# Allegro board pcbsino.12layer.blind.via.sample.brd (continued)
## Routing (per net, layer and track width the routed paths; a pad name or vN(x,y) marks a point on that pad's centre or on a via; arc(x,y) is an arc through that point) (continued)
SODIMM_VIN4A_D7: length 35.7
  TOP w0.114: U6.A10 v2(33.65,17.51)
  INT_L3 w0.091: v3(33.74,16.99) 33.65,17.08 v2(33.65,17.51)
  SIG_L5 w0.091: v3(33.74,16.99) 33.42,16.67 33.42,15.71 34.51,14.62 42.62,14.62 46.47,18.46 46.47,20.13 46.83,20.49 v3(46.83,22.52)
  SIG_L10 w0.091: v5(46.74,22.92) 46.74,22.6 v3(46.83,22.52)
  BOTTOM w0.114: v5(46.74,22.92) 46.77,22.95 48.05,22.95 48.89,23.79 51.48,23.79 52.77,25.08 54.32,25.08 56.02,26.78 XP1.76
SODIMM_VIN4A_D8: length 55.2
  TOP w0.12: v8(35.87,20.77) U6.E8
  SIG_L5 w0.091: v3(46.9,45.5) 46.35,44.95 46.35,42.34
  SIG_L5 w0.094: v8(35.87,20.77) 36.29,20.35 36.29,17.31 37.31,16.29 42.12,16.29 44.32,18.48 44.32,21.75 44.72,22.15 44.72,24.73 45.61,25.62 45.61,25.8 46.35,26.54 46.35,42.34
  SIG_L10 w0.091: v3(46.9,45.5) v5(47.39,45.5)
  BOTTOM w0.114: XP1.124 54.58,41.18 51.2,44.56 50.28,44.56 49.32,45.53 47.42,45.53 v5(47.39,45.5)
SODIMM_VIN4A_D9: length 46
  TOP w0.12: v8(35.07,19.97) U6.D9
  SIG_L10 w0.091: v5(50.59,45.15) 49.63,45.15 44.66,40.17 44.66,39.99 44.66,35.2 44.9,34.95 44.9,34.77 44.9,24.38 44.79,24.27 43.39,22.86 43.02,22.86 42.09,22.86 41.94,22.86 41.26,22.18 41.26,22.13 40.3,21.17 35.61,21.17 35.48,21.04 35.48,20.38 v8(35.07,19.97)
  BOTTOM w0.114: v5(50.59,45.15) 51.02,45.15 54.39,41.78 XP1.126
SODIMM_VIN4A_D10: length 47.4
  TOP w0.12: v8(36.67,19.97) U6.D7
  SIG_L10 w0.091: v5(52.34,44.46) 49.56,44.46 45.43,40.33 45.43,37.1 46.06,36.47 46.06,34.28 45.36,33.58 45.36,23.93 46.09,23.21 46.09,22.17 46.08,22.17 46.08,20.63 45.23,19.77 40.45,19.77 39.92,20.31 39.23,20.31 38.5,19.57 37.07,19.57 v8(36.67,19.97)
  BOTTOM w0.114: v5(52.34,44.46) 52.9,44.46 54.93,42.43 58.58,42.43 XP1.128
SODIMM_VIN4A_D11: length 44.2
  TOP w0.12: v8(35.87,19.97) U6.D8
  SIG_L10 w0.091: v8(35.87,19.97) 36.24,20.35 36.82,20.35 37.19,20.71 40.16,20.71 41.48,22.04 41.48,22.09 42.03,22.64 43.11,22.64 43.48,22.64 44.34,23.5 45.14,24.31 45.14,35.02 44.87,35.29 44.87,40.08 49.59,44.79 v5(52.6,44.79)
  BOTTOM w0.114: v5(52.6,44.79) 53.05,44.79 55.06,42.79 57.04,42.79 57.23,42.98 XP1.130
SODIMM_VIN4A_D12: length 46.6
  TOP w0.12: U6.A5 37.87,17.62 v2(37.79,17.54) 37.79,17.53 37.78,17.53
  INT_L3 w0.091: v2(37.79,17.54) 38.22,17.54 v3(38.27,17.49)
  SIG_L10 w0.091: v3(38.27,17.49) 39.36,16.4 43.35,16.4 47.97,21.02 47.97,26.02 47.28,26.72 46.3,27.7 46.3,29.48 46.03,29.75 46.03,33.32 46.46,33.76 46.72,34.01 46.72,36.2 46.72,36.74 46.09,37.37 46.09,40.06 49.7,43.68 55.72,43.68 56.25,44.21 v5(57.55,44.21)
SODIMM_VIN4A_D13: length 47.4
  TOP w0.12: U6.C6 37.07,19.45 37.35,19.17 v8(37.47,19.17)
  SIG_L10 w0.091: v8(37.47,19.17) 38.29,19.17 39.22,18.24 44.35,18.24 47.44,21.33 47.44,25.8 45.99,27.25 45.59,27.65 45.59,33.5 46.28,34.19 46.28,36.56 45.65,37.19 45.65,40.24 49.54,44.13 55.41,44.13 56.1,44.82 v5(56.94,44.82)
  BOTTOM w0.114: XP1.136 57.03,44.78 56.99,44.82 v5(56.94,44.82)
SODIMM_VIN4A_D14: length 52
  TOP w0.12: v8(35.87,19.17) U6.C8
  SIG_L10 w0.091: v5(58.13,45.38) 58.12,45.36 58.12,44.35 57.47,43.7 56.15,43.7 55.91,43.46 49.79,43.46 46.31,39.97 46.31,37.46 46.94,36.83 46.94,36.11 46.94,33.92 46.42,33.41 46.25,33.23 46.25,29.84 46.51,29.57 46.51,27.79 47.37,26.94 48.19,26.11 48.19,20.91 43.47,16.18 37.5,16.18 36.27,17.41 36.27,18.34 35.87,18.75 v8(35.87,19.17)
SODIMM_VIN4A_D15: length 48.6
  TOP w0.12: v8(36.67,19.17) U6.C7
  SIG_L10 w0.091: v8(36.67,19.17) 36.81,19.17 37.24,18.75 38,18.75 38.73,18.02 44.59,18.02 47.74,21.17 47.74,25.81 46.08,27.47 46.08,29.39 45.81,29.66 45.81,33.41 46.37,33.98 46.5,34.1 46.5,36.29 46.5,36.65 45.87,37.28 45.87,40.15 49.63,43.91 55.55,43.91 56.13,44.49 57.19,44.49 57.65,44.95 57.65,45.97 v5(57.68,45.99)
SODIMM_VIN4A_D16: length 48.3
  TOP w0.114: U6.F11 v8(33.47,21.57)
  SIG_L10 w0.091: v4(41.58,40.63) 41.93,40.28 41.93,33.9 42.1,33.73 42.1,29.68 40.81,28.38 37.79,28.38 35.48,26.07 34.13,26.07 33.85,25.79 33.85,24.53 32.88,23.56 32.25,23.56 31.46,22.77 31.46,22.1 31.62,21.94 32.93,21.94 33.3,21.57 v8(33.47,21.57)
  GND_L11 w0.091: v5(41.72,40.98) v4(41.58,40.63)
  BOTTOM w0.114: v5(41.72,40.98) 50.23,40.98 53.33,37.88 54.8,37.88 56.91,35.78 XP1.106
SODIMM_VIN4A_D17: length 42.7
  TOP w0.12: U6.G10 v8(34.27,22.37)
  SIG_L10 w0.091: v5(44.52,42.2) 43.44,41.12 43.44,39.11 42.59,38.27 42.59,34.17 42.84,33.92 42.84,29.25 39.79,26.2 38.24,26.2 37.92,25.87 37.92,25.24 37.61,24.93 37.36,24.93 35.22,22.8 34.69,22.8 v8(34.27,22.37)
  BOTTOM w0.114: XP1.108 56.77,36.38 55.02,38.13 53.65,38.13 50.18,41.59 45.13,41.59 v5(44.52,42.2)
SODIMM_VIN4A_D18: length 46.5
  TOP w0.114: U6.F10 v8(34.27,21.57)
  SIG_L10 w0.091: v8(34.27,21.57) 34.31,21.57 34.73,22 35.22,22 35.44,22.22 35.44,22.54 36.49,23.58 40.25,23.58 40.47,23.8 43.09,23.8 43.88,24.6 43.88,34.74 43.78,34.84 43.78,39.63 43.78,40.91 44.95,42.08 v5(44.95,42.81)
  BOTTOM w0.114: XP1.110 56.6,36.98 55.21,38.37 53.96,38.37 50.27,42.05 45.71,42.05 v5(44.95,42.81)
SODIMM_VIN4A_D19: length 45.7
  TOP w0.114: U6.G11 v8(33.47,22.37)
  SIG_L10 w0.091: v8(33.47,22.37) 33.88,22.78 33.88,23.39 34.08,23.59 34.92,23.59 35.09,23.76 35.09,24.04 34.92,24.22 34.92,24.79 35.29,25.16 36.8,25.16 37.08,25.44 37.08,25.74 37.86,26.53 39.81,26.53 42.56,29.28 42.56,33.89 42.37,34.08 42.37,41.22 44.82,43.68 v5(45.41,43.68)
  BOTTOM w0.114: v5(45.41,43.68) 46.55,42.53 50.15,42.53 54.07,38.61 55.39,38.61 56.42,37.58 XP1.112
SODIMM_VIN4A_D20: length 58.1
  TOP w0.12: v8(35.07,20.77) U6.E9
  SIG_L5 w0.094: v3(48,45) 46.79,43.79 46.79,34.34 46.79,33.8 46.79,32.22 46.79,27.81 46.81,27.79 46.81,25.2 45.53,23.92 45.53,22.03 44.98,21.48 44.98,18.21 42.26,15.49 36.6,15.49 35.84,16.25 35.84,16.85 35.33,17.36 35.33,18.04 35.47,18.19 35.47,20.37 v8(35.07,20.77)
  SIG_L10 w0.091: v5(47.77,44.21) 48,44.44 v3(48,45)
  BOTTOM w0.114: XP1.116 55.89,38.78 55.64,39.03 53.99,39.03 48.81,44.21 v5(47.77,44.21)
SODIMM_VIN4A_D21: length 45.9
  TOP w0.12: v8(35.07,21.57) U6.F9
  SIG_L10 w0.091: v5(47.06,44.23) 47.06,43.78 44,40.72 44,40.44 44,34.93 44.14,34.79 44.14,24.54 43.18,23.58 43,23.58 40.56,23.58 40.25,23.28 39.71,23.28 39.22,22.8 37.31,22.8 37.3,22.81 36.53,22.81 36.24,22.53 36.24,22.22 36.02,22 35.53,22 35.11,21.57 v8(35.07,21.57)
  BOTTOM w0.114: v5(47.06,44.23) 47.34,44.51 48.85,44.51 53.98,39.38 XP1.118
SODIMM_VIN4A_D22: length 44.8
  TOP w0.12: U6.F8 35.83,21.61 35.83,21.57 v8(35.84,21.56)
  SIG_L10 w0.091: v5(48.79,44.84) 48.79,44.64 44.44,40.29 44.44,40.26 44.44,35.11 44.69,34.86 44.69,24.47 44.57,24.36 43.3,23.08 43.11,23.08 42.18,23.08 41.81,23.08 41.04,22.32 41.04,22.22 40.78,21.96 36.47,21.96 36.08,21.57 35.85,21.57 v8(35.84,21.56)
  BOTTOM w0.114: v5(48.79,44.84) 48.94,44.84 53.8,39.98 XP1.120
SODIMM_VIN4A_D23: length 45.9
  TOP w0.12: v8(36.67,20.77) U6.E7
  SIG_L5 w0.091: v8(36.67,20.77) 37.04,21.15 37.04,22.53 37.02,22.55 37.02,25.17 37.1,25.25 37.1,25.85 37.01,25.94 37.01,27.93 36.8,28.15 36.65,28.15 35.48,29.32 35.48,32.91 35.49,32.92 35.49,32.93 35.71,33.15 35.72,33.15 36.01,33.44 36.01,33.92 37.09,35 37.09,35.33 37.31,35.55 38.5,35.55 38.69,35.74 38.69,36.13 38.91,36.35 39.3,36.35 39.52,36.57 39.52,37.06 40.53,38.06 41.55,38.06 v3(42.79,39.31)
  SIG_L10 w0.091: v3(42.79,39.31) 42.79,41.21 44.82,43.24 45.53,43.24 47.11,44.82 v5(47.11,44.92)
  BOTTOM w0.114: XP1.122 53.66,40.58 49.09,45.15 47.39,45.15 47.16,44.92 v5(47.11,44.92)
SODIMM_VIN4A_DE0: length 50.5
  TOP w0.114: v2(34.15,18.48) 33.87,18.77 U6.B10
  INT_L3 w0.091: v3(34.24,17.92) 34.15,18 v2(34.15,18.48)
  SIG_L5 w0.091: v3(47.87,37.76) 47.25,37.14 47.25,24.49 46.43,23.67 46.43,20.4 46.25,20.22 46.25,18.55 42.53,14.84 34.6,14.84 34.23,15.21 34.23,15.54 34.24,15.54 v3(34.24,17.92)
  SIG_L10 w0.091: v3(47.87,37.76) 47.87,38.44 v5(48,38.57)
  BOTTOM w0.114: v5(48,38.57) 48.3,38.88 50.87,38.88 52.1,37.64 54.64,37.64 57.1,35.18 XP1.104
SODIMM_VIN4A_FLD0: length 54.3
  TOP w0.12: v8(33.5,19.88) 33.49,19.88 33.49,19.95 U6.D11
  SIG_L10 w0.091: v5(48.33,37.07) 48.05,36.8 48.05,34.04 48.05,33.5 47.84,33.28 47.34,32.78 47.34,30.29 48.02,29.6 48.02,28.05 49.53,26.55 49.53,20.57 43.68,14.72 34.23,14.72 33.32,15.63 33.32,17.81 34,18.5 34,19.37 v8(33.5,19.88)
  BOTTOM w0.114: v5(48.33,37.07) 48.33,37.03 48.59,36.77 54.12,36.77 56.61,34.28 56.61,33.9 57.13,33.38 XP1.98
SODIMM_VIN4A_HSYNC0: length 52
  TOP w0.12: v8(33.51,19.23) 33.49,19.24 33.4,19.24 U6.C11
  SIG_L5 w0.091: v8(33.51,19.23) 33.62,19.12 33.62,17.48 33,16.86 33,15.47 34.06,14.4 42.9,14.4 46.69,18.19 46.69,20.04 47.47,20.82 47.47,34.02 48.59,35.14 49.48,35.14 50.46,36.12 50.46,37.62 v3(50.29,37.79)
  SIG_L10 w0.091: v3(50.29,37.79) 50.77,37.79 v5(50.77,37.78)
  BOTTOM w0.114: v5(50.77,37.78) 50.85,37.71 50.87,37.71 51.48,37.1 54.17,37.1 57.29,33.98 XP1.100
SODIMM_VIN4A_VSYNC0: length 55.5
  TOP w0.12: v8(33.47,20.77) U6.E11
  SIG_L10 w0.091: v8(33.47,20.77) 33.47,20.51 34.41,19.57 34.41,18.43 34.66,18.17 34.66,17.16 34.23,16.73 34.23,15.15 34.44,14.94 43.59,14.94 49.31,20.66 49.31,26.21 49.28,26.24 49.28,26.26 47.73,27.81 47.73,29.59 47.12,30.2 47.12,32.87 47.84,33.59 47.84,33.95 47.84,37.06 48.27,37.5 48.27,38.29 v5(48.48,38.49)
  BOTTOM w0.114: XP1.102 57.17,34.58 54.4,37.35 51.91,37.35 50.69,38.57 48.56,38.57 v5(48.48,38.49)
SODIMM_VIN5A_D8: length 55.4
  TOP w0.12: v8(39.07,34.37) U6.AA4
  INT_L3 w0.091: v2(57.7,4.59) 58.11,4.59 58.64,4.05 58.64,2.22 57.85,1.44 v3(56.53,1.44)
  SIG_L8 w0.091: v8(39.07,34.37) 39.49,33.95 40.27,33.95 40.48,33.74 45.01,33.74 46.85,35.59 49.33,35.59 49.6,35.85 v3(49.6,35.9)
  SIG_L10 w0.091: v3(49.6,35.9) 51.65,33.85 51.65,22.3 51.9,22.05 52.03,21.92 52.03,21.27 52.03,21.26 52.03,20.83 52.03,20.83 52.03,18.34 51.76,18.07 51.63,17.94 51.63,11.41 54.04,9 54.04,4.86 56.38,2.53 56.38,1.59 v3(56.53,1.44)
SODIMM_VIN5A_D9: length 53
  TOP w0.12: v8(39.87,35.17) U6.AB3
  INT_L3 w0.091: v2(57.95,3.98) 58.18,3.98 58.41,3.75 58.41,2.43 57.73,1.74 56.79,1.74 56.7,1.84 56.69,1.84 56.3,2.22 v3(55.95,2.22)
  SIG_L8 w0.091: v8(39.87,35.17) 40.82,34.22 44.86,34.22 46.81,36.16 48.31,36.16 48.35,36.21 v3(48.45,36.21)
  SIG_L10 w0.091: v3(55.95,2.22) 55.87,2.3 55.87,2.53 53.82,4.57 53.82,8.77 51.27,11.32 51.27,17.89 51.41,18.03 51.81,18.43 51.81,20.92 51.81,20.92 51.81,21.17 51.81,21.18 51.81,21.83 51.67,21.97 51.05,22.59 51.05,30.47 50.59,30.92 50.59,34.25 49.14,35.7 49.14,35.93 48.86,36.21 v3(48.45,36.21)
SODIMM_VIN5A_D10: length 52
  TOP w0.114: XP1.3 56.51,2.78 v2(56.48,2.81) ; U6.AB9 v2(35.07,35.14)
  INT_L3 w0.091: v2(35.07,35.14) 35.04,35.14 34.89,35 34.89,34.56 v3(34.88,34.55) ; v3(41.77,11.09) 41.72,11.04 41.72,9.92 43.45,8.19 46.63,8.19 46.85,7.97 46.85,6.65 47.79,5.71 50.43,5.71 52.12,4.02 52.13,4.02 52.36,3.79 52.36,3.78 52.54,3.59 54.5,3.59 54.71,3.39 54.73,3.38 54.99,3.21 55.2,2.99 55.32,2.81 v2(56.48,2.81)
  SIG_L8 w0.091: v3(41.77,11.09) 42.66,11.98 42.66,15.61 41.09,17.18 41.09,17.81 38.79,20.11 38.79,20.91 37.74,21.96 37.18,21.96 37.08,22.06 37.08,28.69 36.34,29.43 36.34,29.75 35.4,30.7 34.89,30.7 34.64,30.94 34.64,31.33 34.42,31.55 34.04,31.55 33.85,31.73 33.85,33.72 34.13,34 34.43,34 34.88,34.44 v3(34.88,34.55)
SODIMM_VIN5A_D11: length 50.4
  TOP w0.12: v8(39.83,34.34) U6.AA3
  INT_L3 w0.091: v2(58.01,3.39) 58.01,2.91 v3(57.83,2.73)
  SIG_L8 w0.091: v8(39.83,34.34) 40.27,34.34 40.61,34 44.95,34 46.76,35.81 48.87,35.81 49.39,36.34 50,36.34 v3(50.06,36.28)
  SIG_L10 w0.091: v3(50.06,36.28) 51.87,34.47 51.87,22.39 51.99,22.27 52.24,22.01 52.24,21.36 52.25,21.35 52.25,20.74 52.24,20.74 52.24,18.25 51.99,17.99 51.85,17.85 51.85,11.5 54.35,9 54.35,5.02 56.63,2.73 v3(57.83,2.73)
SODIMM_VIN5A_D12: length 51.9
  TOP w0.12: v8(27.87,19.97) U6.D17
  INT_L3 w0.091: v3(44.04,6.97) 44.34,6.97 44.85,6.46 44.85,3.24 47.66,0.43 58.04,0.43 59.3,1.68 59.3,2.01 59.3,5.56 58.82,6.03 v2(58.82,7)
  SIG_L10 w0.091: v8(27.87,19.97) 27.99,19.97 28.6,19.36 28.6,12.65 29.48,11.78 30.27,11.78 34.86,7.19 43.82,7.19 v3(44.04,6.97)
SODIMM_VIN5A_D13: length 45.2
  TOP w0.114: XP1.15 v2(57.53,6.38)
  TOP w0.12: v8(28.67,22.37) U6.G16
  INT_L3 w0.091: v2(57.53,6.38) 56.74,6.38 56.42,6.06 53.54,6.06 v3(53.34,5.87)
  SIG_L10 w0.091: v3(53.34,5.87) 51.79,5.87 51.52,6.14 47.17,6.14 46.73,5.71 44.91,5.71 44.11,6.52 43.53,6.52 43.44,6.61 36.63,6.61 36.3,6.95 36.12,6.95 34.79,6.95 30.18,11.56 29.39,11.56 28.38,12.56 28.38,19.19 28.02,19.55 27.71,19.55 27.47,19.79 27.47,20.94 27.73,21.2 28.09,21.2 28.29,21.41 28.29,21.96 28.67,22.34 v8(28.67,22.37)
SODIMM_VIN5A_D14: length 50.8
  TOP w0.114: U6.A21 25.87,17.17 25.87,14.06 v2(25.32,13.5)
  INT_L3 w0.091: v3(24.78,13.42) 24.86,13.5 v2(25.32,13.5) ; v3(45.76,4.33) 45.82,4.33 46.6,5.11 50.14,5.11 51.56,3.69 51.56,3.13 51.71,2.98 53.11,2.98 53.16,3.04 53.38,3.18 53.62,3.28 53.87,3.33 54.13,3.33 54.39,3.28 54.63,3.18 54.85,3.04 55.03,2.85 55.18,2.64 55.28,2.4 55.33,2.14 55.33,1.56 56,0.89 57.72,0.89 58.86,2.03 58.86,4.37 v2(58.06,5.17)
  SIG_L10 w0.091: v3(45.76,4.33) 43.76,4.33 43.1,4.99 34.04,4.99 33.88,4.83 33.15,4.83 32.18,5.81 32.08,5.81 24.78,13.11 v3(24.78,13.42)
SODIMM_VIN5A_D15: length 50
  TOP w0.12: v8(27.04,19.22) 27.05,19.22 27.07,19.24 27.13,19.24 U6.C18
  INT_L3 w0.091: v2(58.06,5.8) 59.08,4.78 59.08,1.87 57.88,0.67 47.87,0.67 45.33,3.22 45.33,5.19 v3(45.41,5.27)
  SIG_L10 w0.091: v8(27.04,19.22) 27.37,18.89 27.37,14.96 27.27,14.85 27.27,13.04 33.57,6.74 34.68,6.74 34.7,6.73 36.21,6.73 36.54,6.39 43.35,6.39 43.44,6.3 43.92,6.3 44.98,5.25 45.38,5.25 v3(45.41,5.27)
SODIMM_WAKEUP1/GPIO1_1: length 53.4
  TOP w0.12: v8(27.87,35.97) U6.AC17
  SIG_L5 w0.091: v7(53.18,63.46) 52.62,63.46 51.53,62.37 51.53,54.98 49.57,53.02 45.38,53.02 42.24,49.88 42.24,49.2 41.22,48.17 41.22,44.82 40.83,44.44 31.77,44.44 29.07,41.75 29.07,36.36 28.69,35.97 v8(27.87,35.97)
  BOTTOM w0.114: XP1.192 55.52,61.58 R59.1 55.26,61.99 53.79,63.46 v7(53.18,63.46)
SODIMM_WARM_RESETN: length 90.3
  TOP w0.114: R54.2 20.02,3.68 C55.1 ; C55.1 21.23,3.68 21.52,3.96 v2(21.57,3.96) ; C55.1 20.62,3.94 U5.1 ; XP1.187 v2(57.95,60.38)
  INT_L3 w0.091: v3(21.81,4.38) 21.83,4.36 21.83,4.23 v2(21.57,3.96) ; v2(57.95,60.38) 57.95,60.37 57.95,60.09 v3(58.06,59.98)
  SIG_L5 w0.091: v3(58.06,59.98) 58.73,59.31 58.73,30.8 54.91,26.99 54.91,22.17 55.52,21.57 55.52,15.09 48.12,7.69 45.99,7.69 44.91,6.61 44.91,6.11 43.59,4.79 38.18,4.79 37.96,4.56 36.84,4.56 36.71,4.69 22.12,4.69 v3(21.81,4.38)
SYS_WARMRESETN: length 17.4
  TOP w0.114: v2(19.38,8.1) C59.1 18.22,7.83 U5.4
  TOP w0.12: v8(23.07,20.77) U6.E23
  INT_L3 w0.091: v8(23.07,20.77) 22.76,20.46 22.76,19.96 22.35,19.55 22.11,19.55 21.89,19.33 21.89,16.03 20.06,14.2 20.06,14.02 20.06,12.21 20.46,11.8 20.46,10.07 19.85,9.46 19.85,8.58 v2(19.38,8.1)
SYSBOOT0: length 2.3
  TOP w0.12: v8(37.46,27.19) 37.46,27.16 U6.M6
  BOTTOM w0.114: R224.2 R225.1 37.15,27.5 v8(37.46,27.19)
SYSBOOT1: length 6.3
  TOP w0.114: R222.2 R223.1 44.82,26.48 43.1,26.48 42.49,27.09 41.84,27.09 41.76,27.17 40.66,27.17 40.27,26.78 U6.M2
SYSBOOT2: length 3.4
  TOP w0.12: v8(38.3,25.56) 38.24,25.62 38.23,25.62 U6.L5
  BOTTOM w0.114: R220.2 R221.1 39.8,26.69 39.54,26.43 39.16,26.43 v8(38.3,25.56)
SYSBOOT3: length 7.4
  TOP w0.114: R218.2 47.48,25.36 R219.1
  TOP w0.12: R219.1 46.64,26.2 42.99,26.2 42.42,26.77 U6.M1
SYSBOOT4: length 39.7
  TOP w0.12: v8(37.48,25.56) U6.L6
  SIG_L5 w0.091: v3(52.09,50.75) 52.05,50.75 51.82,50.51 49.9,50.51 48.51,49.11 46.73,49.11 46.25,48.63 46.25,46.55 44.82,45.12 44.82,40.38 41.95,37.5 40.87,37.5 40.29,36.93 40.29,35.06 40.03,34.8 37.29,34.8 36.29,33.8 36.29,29.24 37.83,27.7 37.83,25.94 37.48,25.58 v8(37.48,25.56)
  SIG_L10 w0.091: v5(52.54,50.9) 52.28,50.9 52.12,50.75 v3(52.09,50.75)
  BOTTOM w0.114: R217.1 R216.2 52.56,52.45 R329.2
SYSBOOT5: length 39.9
  TOP w0.12: v8(39.07,25.57) U6.L4
  SIG_L5 w0.091: v3(53.02,50.75) 52.45,50.18 50,50.18 46.97,47.15 46.97,46.65 45.43,45.12 45.43,36.39 45.16,36.12 45.16,28.47 44.85,28.16 44.85,25.97 43.1,24.22 40.48,24.22 39.13,25.57 v8(39.07,25.57)
  SIG_L10 w0.091: v5(53.48,50.97) 53.37,50.86 53.18,50.86 53.06,50.75 v3(53.02,50.75)
  BOTTOM w0.114: 53.59,50.97 v5(53.48,50.97) 53.56,50.9 53.56,50.8 53.59,50.76 R212.2 53.59,50.97 ; 53.59,50.97 R214.1 53.59,51.63 R324.2
SYSBOOT6: length 2.3
  TOP w0.12: v8(39.79,25.51) 39.79,25.59 39.47,25.92 U6.L3
  BOTTOM w0.114: R207.2 R208.1 40.27,25.99 v8(39.79,25.51)
SYSBOOT7: length 8.6
  TOP w0.114: U6.L2 40.68,26.39 42.35,26.39 42.84,25.9 45.79,25.9 47.1,24.59 R206.1 R205.2
SYSBOOT8: length 8.3
  TOP w0.114: R204.1 R203.2
  TOP w0.12: R204.1 47.1,23.73 46.7,24.13 45.86,24.13 45.69,24.3 45.69,25.13 45.23,25.59 42.74,25.59 42.36,25.97 U6.L1
SYSBOOT9: length 9.8
  TOP w0.114: U6.K2 40.66,25.57 41.73,25.57 41.86,25.69 42.18,25.69 42.54,25.34 45.13,25.34 45.33,25.13 45.33,23.76 45.8,23.29 46.7,23.29 47.1,22.89 R202.1 R201.2
SYSBOOT10: length 9.3
  TOP w0.114: U6.J1 41.95,24.37 41.97,24.36 43.62,24.36 44.17,23.81 44.17,21.88 44.38,21.67 46.72,21.67 47.1,22.05 R200.1 R199.2
SYSBOOT11: length 10.6
  TOP w0.114: U6.J2 40.65,23.99 43.58,23.99 43.86,23.71 43.86,21.83 44.31,21.37 45.25,21.37 45.86,20.76 46.96,20.76 47.1,20.91 R198.1 R197.2
SYSBOOT12: length 3.3
  TOP w0.114: R194.2 R196.1
  TOP w0.12: U6.H1 42.14,23.57 43.11,22.6 R196.1
SYSBOOT13: length 6.6
  TOP w0.114: U6.J3 39.54,24.37 39.95,24.78 41.89,24.78 42.07,24.6 43.98,24.6 44.76,23.82 R191.1 R190.2
SYSBOOT14: length 10.5
  TOP w0.114: R185.2 47.43,20.41 R184.1 47.13,19.87 46.93,19.67 45.61,19.67 44.85,20.43 44.16,20.43
  TOP w0.12: 44.16,20.43 42.69,20.43 42.31,20.82 42.31,22.24 41.36,23.19 40.66,23.19 U6.H2
SYSBOOT15: length 2.3
  TOP w0.114: v8(39.87,23.97) 39.48,23.57 U6.H3
  BOTTOM w0.114: R182.2 R183.1 39.95,24.04 v8(39.87,23.97)
TCK: length 27.8
  TOP w0.114: R171.1 12.17,4.5 12.36,4.31 12.36,4.05 12.86,3.55 R155.2 ; U6.E20 v2(25.47,20.79)
  INT_L3 w0.091: v2(12.08,4.64) 12.08,4.69 12.64,5.25 18.74,5.25 22.29,8.8 22.29,10.66 23.98,12.34 23.98,13.82 24.15,13.99 24.15,14.03 24.22,14.1 24.57,14.45 24.57,15.42 25.47,16.32 25.47,17.92 25.72,18.17 25.72,19.09 25.11,19.7 25.11,20.42 25.47,20.77 v2(25.47,20.79)
TCLK: length 1.6
  TOP w0.114: P1.11 11.96,2.61 R171.2
TDI: length 23.6
  TOP w0.114: U6.D23 23.45,20.37 v2(23.05,19.98) ; P1.3 16.44,2.16 15.31,3.29 15.31,5.14 v2(15.97,5.8)
  INT_L3 w0.091: v2(15.97,5.8) 17.72,5.8 20.69,8.78 20.69,12.08 20.28,12.49 20.28,14.11 22.14,15.97 22.14,18.38 22.72,18.96 22.72,19.47 23.05,19.8 v2(23.05,19.98)
TDO: length 1.7
  TOP w0.114: R166.2 14.78,2.89 P1.7
TDOR: length 25.4
  TOP w0.114: U6.F19 v2(26.26,21.55)
  INT_L3 w0.091: v2(26.26,21.55) 26.65,21.16 26.65,19.19 26.66,19.18 26.66,18.18 26.26,17.79 26.26,16.89 26.29,16.86 26.29,16.85 26.61,16.52 26.61,15.81 25.77,14.97 25.77,13.23 22.92,10.38 22.92,10.2 22.92,8.69 18.41,4.18 15.16,4.18 v2(14.93,4.41)
TMS: length 27.9
  TOP w0.114: P1.1 17.09,2.93 16.43,2.93 R156.2 ; U6.F18 v2(27.09,21.6)
  INT_L3 w0.091: v2(27.09,21.6) 27.55,21.15 28.15,21.15 28.29,21.01 28.29,18 28.49,17.79 28.49,16.19 27.52,15.22 27.52,14.34 27.43,14.26 27.43,14.16 23.54,10.27 23.54,9.72 23.54,7.84 P1.1
TRSTN: length 25.8
  TOP w0.114: R158.1 16.92,4.5 ; 16.92,4.5 17.15,4.5 17.3,4.65 v2(17.3,4.66) ; 16.92,4.5 18.69,2.73 18.69,1.61 17.96,0.89 P1.2 ; U6.D20 v2(25.52,20)
  INT_L3 w0.091: v2(17.3,4.66) 17.31,4.66 17.44,4.53 18.38,4.53 22.7,8.86 22.7,10.11 22.7,10.47 24.2,11.97 24.2,13.73 24.76,14.29 24.76,14.33 24.79,14.36 24.79,14.88 25.85,15.94 25.85,16.68 25.82,16.71 25.82,17.97 25.98,18.12 25.98,19.24 25.47,19.75 25.47,19.95 v2(25.52,20)
USB1_TX0_N: length 40.4
  TOP w0.127: U6.AC11 v6(33.45,35.2)
  SIG_L10 w0.089: v6(33.45,35.2) 33.71,35.46 33.98,35.46 34.17,35.65 36.81,35.65 37.37,36.21 37.37,37.26 39.74,39.64 39.74,41.07 42.12,43.45 42.12,50.51 46.45,54.84 49.51,54.84 49.66,54.69 49.66,54.53 v5(49.5,54.37)
  BOTTOM w0.102: C166.1 54.01,60.82 53.91,60.72 53.91,60.61 53.81,60.51 52.43,60.51 51.12,59.2 51.12,57.75 49.67,56.3 49.67,54.55 v5(49.5,54.37)
USB1_TX0_P: length 40.4
  TOP w0.127: U6.AD11 v6(33.45,36)
  SIG_L10 w0.089: v5(50,54.34) 49.9,54.45 49.9,54.79 49.61,55.08 46.35,55.08 41.88,50.61 41.88,43.55 39.5,41.17 39.5,39.74 37.13,37.36 37.13,36.31 36.71,35.89 34.07,35.89 33.88,35.7 33.62,35.7 33.45,35.87 v6(33.45,36)
  BOTTOM w0.102: v5(50,54.34) 49.93,54.42 49.93,56.19 51.38,57.64 51.38,59.09 52.54,60.25 53.81,60.25 53.91,60.15 53.91,60.04 54.01,59.94 C165.1
USER_LED_BLUE: length 46.4
  TOP w0.114: v2(32.71,19.9) 32.71,19.93 U6.D12 ; Q6.G 45.01,5.63 R239.2 44.64,6.14 v2(44.29,6.49)
  INT_L3 w0.091: v2(44.29,6.49) 44.24,6.54 42.26,6.54 38.91,3.2 37.46,3.2 37.08,2.82 26.45,2.82 23.98,5.29 23.98,10.09 26.75,12.86 30.49,12.86 32.91,15.28 32.91,16.78 32.28,17.41 32.28,17.77 31.98,18.07 31.98,18.97 32.71,19.7 v2(32.71,19.9)
USER_LED_GREEN: length 44
  TOP w0.114: R237.2 42.75,5.87 Q4.G ; U6.F13 31.39,21.95 31.18,21.6 31.1,21.58 v2(31.08,21.55)
  INT_L3 w0.091: v2(31.08,21.55) 30.67,21.55 30.11,20.99 30.11,13.98 29.21,13.07 26.66,13.07 23.76,10.18 23.76,9.81 23.76,5.2 26.36,2.6 37.17,2.6 37.55,2.98 39.1,2.98 42.03,5.91 v2(42.61,5.91)
USER_LED_RED: length 40.8
  TOP w0.114: U6.C12 v2(32.7,19.2) ; R238.2 40.34,5.94 Q5.G
  INT_L3 w0.091: v2(40.3,5.98) 40.28,5.96 40.28,5.09 38.6,3.42 37.37,3.42 36.99,3.04 26.54,3.04 24.2,5.38 24.2,10 26.84,12.64 30.6,12.64 33.21,15.25 33.21,17.54 33.62,17.94 33.62,18.59 33.36,18.84 33.36,18.84 33.15,19.06 33.14,19.06 33.06,19.14 32.76,19.14 v2(32.7,19.2)
VREF_DDR: length 20.2
  TOP w0.12: v8(27.07,33.57) U6.Y18
  TOP w0.254: v8(10.73,38.21) 10.33,37.81 U9.H1 ; v8(6.73,20.61) 7.13,21.01 U11.M8 ; U9.M8 7.13,32.21 v8(6.73,31.81) ; U10.M8 7.13,9.81 v8(6.73,9.41) ; U8.H1 10.33,49.01 10.69,49.37 10.69,49.39 v8(10.72,49.42) 10.72,49.45 10.77,49.51 C76.1 ; U2.6 13.41,63.91 13.82,64.33 14.71,64.33 v7(14.82,64.44) C12.1 14.82,65.19 TP3.1 ; U6.N22 v8(23.87,27.17) ; U10.H1 v8(10.73,15.81) ; v8(10.69,27.01) 10.69,26.96 U11.H1 ; v8(6.73,43.01) 7.13,43.41 U8.M8
  TOP w0.381: C74.2 C76.1
  BOTTOM w0.254: v8(23.87,27.17) 24.01,27.03 C139.2 ; C78.1 6.88,31.96 v8(6.73,31.81) ; v8(6.73,9.41) 6.88,9.25 C114.1 ; v8(6.73,20.61) 6.85,20.61 C116.1 ; C102.1 27.14,33.5 v8(27.07,33.57)
  BOTTOM w0.381: C111.2 C113.1 10.54,16 v8(10.73,15.81) ; C77.1 6.81,42.93 v8(6.73,43.01) ; C112.2 C115.1 10.77,27.1 v8(10.69,27.01) ; C75.2 C79.1 10.67,38.27 v8(10.73,38.21)
VSYS_5V0: length 133.5
  TOP w0.114: U3.D13 33.52,50.24 v7(33.52,50.18) ; U3.J3 29.14,58.62 v7(28.74,59.02) ; v7(30.34,50.2) 30.34,50.22 U3.H13 ; v7(28.74,59.83) 29.14,59.44 U3.J2 ; v7(34.33,57.44) 33.94,57.05 U3.C5 ; U3.E3 U3.F2 31.55,59.42 v7(31.94,59.81) 32.33,59.42 U3.E2 U3.F3 ; v7(27.09,54.24) 27.09,54.18 U3.M9 ; v7(32.3,60.78) 32.34,60.74 U3.E1 ; U3.M4 26.74,57.82 v7(26.33,58.23) ; U3.H12 29.94,51.42 v7(30.34,51.02) ; v7(33.52,51.04) 33.14,51.42 U3.D12 ; 53.83,60.09 C6.1 54.05,59.87 ; U3.N3 25.79,58.62 v7(25.47,58.94) ; v7(30.34,52.59) 29.98,52.22 U3.H11 ; v7(34.28,58.18) 34.28,58.13 33.98,57.82 U3.C4 ; v7(25.32,56.22) U3.N6 U3.M6 26.74,56.22 v7(27.13,55.83) ; U3.F1 31.54,60.62 v7(31.68,60.76) 31.68,60.99 v7(32,61.31) ; U3.M8 26.36,54.24 v7(26.36,54.22) 25.96,53.82 U3.N9 25.83,53.82 v7(25.47,54.19) 25.51,54.19 U3.N8 ; U3.N4 25.85,57.82 v7(25.47,58.2) ; C4.1 53.93,58.14 54.05,58.26 v7(54.05,58.13) ; v2(44.37,58.99) 44.39,58.97 44.84,58.97 R23.1 ; U3.G11 v7(30.33,51.82)
  TOP w0.254: R8.2 50.85,53.45 51.2,53.1 51.2,52.95 R27.1 51.66,52.46 51.02,51.83 50.64,51.83 50.03,51.22 49.06,51.22 R4.2 48.48,51.68 47.99,51.19 45.6,51.19 U4.5 45.19,51.38 44.52,52.06 42.03,52.06 41.24,51.27 R48.2 40.82,51.02 40.56,50.76 39.26,50.76 38.82,51.2 R44.1 ; R227.1 R228.1 v2(21.79,1.69) R229.1 ; R23.1 44.9,59.25 ; 44.9,59.25 R9.1 ; 44.9,59.25 44.65,58.99 v2(44.37,58.99) ; v7(32.76,52.62) 33.14,52.24 U3.D11
  TOP w0.381: v7(26.41,50.03) 26.94,50.03 U3.L13 27.54,50.64 27.39,50.79 27.39,51.24 27.41,51.27 27.41,51.3 U3.L12 ; C1.2 49.6,54.06 50.22,53.45 R8.2 50.72,53.71 51.27,54.27 52.51,54.27 52.89,54.65 ; C1.2 49.27,54 U1.5 ; C1.2 49.4,54.33 48.81,54.91 U1.6 ; U3.C7 33.94,55.38 34.12,55.2 34.12,55.17 v7(34.26,55.03) ; v7(36.2,56.35) 36.07,56.22 U3.A6
  INT_L3 w0.254: v2(44.37,58.99) 44.51,58.85 v3(44.51,58.57) 38.89,58.57 v2(38.85,58.53) ; v2(21.79,1.69) 22.24,1.69 v3(22.32,1.61)
  SIG_L5 w0.254: v7(55.97,4.58) 55.17,3.77 53.74,3.77 52.14,2.17 52.14,1.23 51.41,0.51 46.28,0.51 44.06,2.73 38.4,2.73 37.38,1.71 22.42,1.71 v3(22.32,1.61)
  SIG_L10 w0.381: v5(58.11,9.98) 57.9,9.98 57.52,9.6 v3(57.52,8.35) ; v5(58.31,27.39) 58.3,27.38 v3(57.78,27.38)
  BOTTOM w0.114: 35.04,57.47 34.36,57.47 v7(34.33,57.44) ; 35.04,57.47 34.33,58.18 v7(34.28,58.18) ; 35.04,57.47 C50.2 ; XP1.28 v5(58.11,9.98)
  BOTTOM w0.381: XP1.186 56.71,59.78 55.87,58.94 54.86,58.94 v7(54.05,58.13) ; C50.2 35.6,56.99 36.83,56.99 ; C52.1 36.83,56.99 ; 36.83,56.99 v7(36.2,56.35) ; C38.1 35.58,54.12 34.66,55.03 v7(34.26,55.03) ; XP1.114 56.93,38.18 v7(56.79,38.04) ; XP1.168 57.2,54.38 56.91,54.09 v7(56.87,54.09) ; C42.1 25.06,51.37 v7(26.41,50.03) ; XP1.78 58.32,27.38 v5(58.31,27.39) ; XP1.132 57.05,43.58 v7(56.71,43.24) ; XP1.64 v7(56.86,20.78) ; XP1.204 v7(56.76,65.18) ; v7(56.86,32.8) 56.89,32.78 XP1.96 ; XP1.150 57.2,48.98 v7(56.54,49.63) ; XP1.46 v7(56.68,15.38) ; v7(55.97,4.58) XP1.10
  vias: v1(53.36,55.41) v1(53.38,59.04) v1(53.38,57.32) v1(53.41,56.91) v1(53.74,56.38) v1(53.79,57.29) v1(53.81,56.99) v1(53.79,55.66) v1(53.92,59.02) v1(54.45,61.1) v1(54.42,60.59) v1(54.42,60.08) v1(54.42,59.73) v1(54.37,59.02) v2(53.36,55.41) v2(53.38,59.04) v2(53.38,57.32) v2(53.41,56.91) v2(53.74,56.38) v2(53.79,57.29) v2(53.81,56.99) v2(53.79,55.66) v2(53.92,59.02) v2(54.45,61.1) v2(54.42,60.59) v2(54.42,60.08) v2(54.42,59.73) v2(54.37,59.02) v3(49.65,60.21) v3(49.65,59.58) v3(49.65,58.15) v3(50.21,60.8) v3(50.26,60.19) v3(50.23,59.58) v3(50.23,58.15) v3(50.87,60.21) v3(50.87,59.55) v3(50.84,58.18) v3(50.89,60.8) v3(51.12,55.74) v3(53.15,59.75) v3(53.18,61) v3(53.2,60.39) v3(53.84,60.97) v3(53.81,60.39) v3(53.79,59.73) v7(52.9,58.15) v7(53.46,58.15)
VTT_DDR: length 59.8
  TOP w0.114: U2.3 12.41,59.8 13.5,58.71 ; C11.1 C10.1
  TOP w0.254: R15.1 14.51,59.89 13.5,58.88 C11.1
  BOTTOM w0.114: v7(13.48,54.75) 13.48,54.88 13.5,54.9 C9.1
  BOTTOM w0.381: C103.1 C108.1 R113.1 R111.1 R109.1 R122.1 R102.1 8.36,17.38 R125.1 8.37,17.38 8.91,17.38 8.91,17.38 C107.1 ; C109.1 R114.1 R112.1 R110.1 R123.1 R101.1 8.28,6.89 C104.1 ; C71.1 R70.1 R71.1 R72.1 R91.1 R73.1 R75.1 R82.1 R86.1 C67.1 C72.1 R87.1 ; C69.1 6.96,40.73 ; 6.96,40.73 6.96,40.02 R89.1 ; 6.96,40.73 6.88,40.73 6.83,40.68 6.8,40.68 6.36,40.23 6.36,40.2 R76.1 ; R89.1 R69.1 R92.1 ; R89.1 R76.1 ; R116.1 R121.1 R118.1 R107.1 R117.1 R120.1 R119.1 ; R87.1 3.49,34.07 3.93,34.07 ; R87.1 R84.1 R74.1 R85.1 R88.1 R83.1 ; C68.1 R81.1 R79.1 R77.1 R90.1 C70.1 R68.1 ; R76.1 R78.1 R80.1 C66.1 ; 2.86,12.72 R119.1 ; R119.1 R115.1 R108.1 R106.1 R124.1 R105.1 R104.1 R103.1 C106.1 10.18,12.72 C105.1
  vias: v7(12.55,57.04) v7(12.56,55.36)
VUSB_3V3: length 15.2
  TOP w0.254: U6.AA12 v8(32.67,33.57) U6.Y12
  TOP w0.381: U3.B9 34.74,53.81 v7(35.12,53.43)
  INT_L3 w0.381: v2(43.53,52.79) 41.42,52.79 40.99,53.23 35.32,53.23 v7(35.12,53.43)
  SIG_L10 w0.381: v5(34.28,38.47) 34.33,38.42 v3(34.84,38.42)
  BOTTOM w0.114: v8(32.67,33.57) 32.88,33.79 C161.1 33.45,34.13 33.82,34.5 33.82,35.46 C162.1
  BOTTOM w0.381: C31.2 35.78,52.77 v7(35.12,53.43)
  vias: v4(33.98,38.47) v5(33.98,38.47)
N05979: length 98.9
  SIG_L5 w0.091: v7(19.63,11.11) 20.77,11.11 26.25,5.64 32.92,5.64 33.16,5.88 42.01,5.88 45.9,9.76 46.89,9.76 51.83,14.7 51.83,15.56 53.88,17.6 53.88,20.97 51.69,23.15 51.69,29.86 53.51,31.67 53.51,32.98 54.04,33.51 54.04,36.26 56.18,38.4 56.18,47.22 57.27,48.32 57.27,59.19 56.54,59.93 56.54,61.87 56.66,61.99 v7(56.66,63.54)
  BOTTOM w0.114: XP1.200 58.61,64 57.12,64 v7(56.66,63.54) ; v7(19.63,11.11) 19.58,11.16 19.58,13.19 19.6,13.21 19.6,15.27 R320.2 19.73,15.4 R321.2
N17551517: length 4.3
  TOP w0.114: R45.2 37.71,58.41 36.76,57.46 35.28,57.46 35.11,57.63 35.11,58.26 U3.B3
N17551519: length 2.7
  TOP w0.114: U3.A11 36.94,52.22 R44.2
N17551928: length 3.7
  TOP w0.114: U3.B7 35.11,55.05 36.85,55.05 C17.2
N25853972: length 2.2
  TOP w0.114: U3.K7 28.71,55.79 v7(28.71,55.79)
  BOTTOM w0.114: R32.1 28.71,56.24 v7(28.71,55.79) 28.68,55.77 28.47,55.77 27.95,55.25 R31.1
N28613451: length 10.1
  INT_L3 w0.091: v2(32.34,56.22) 33.15,55.42 33.71,55.42 33.95,55.65 34.58,55.65 34.88,55.35 39.23,55.35 v3(39.31,55.44)
  SIG_L10 w0.091: v3(39.31,55.44) 39.49,55.44 v5(39.74,55.18)
  BOTTOM w0.114: v5(39.74,55.18) 39.77,55.18 40.13,54.82 R25.2 R22.2
N28614012: length 2.9
  TOP w0.114: U3.E5 v7(31.97,57.39)
  BOTTOM w0.114: v7(31.97,57.39) 32.17,57.59 R26.2 R24.2 33.07,58.79 R19.2
N28708877: length 7
  TOP w0.114: U3.A2 35.74,59.63 v7(36.31,59.63)
  BOTTOM w0.114: v7(36.31,59.63) 37.33,60.64 C15.1 38.22,60.64 38.83,60.03 40.11,60.03 Y1.1
N29245750: length 6
  TOP w0.12: v8(31.07,37.57) U6.AE14
  BOTTOM w0.114: R64.1 R63.2 31.49,41.24 31.49,39.92 30.6,39.03 30.6,38.04 31.06,37.57 v8(31.07,37.57)
N29975844: length 1.9
  INT_L3 w0.091: v3(34.36,60.97) 33.95,60.57 v2(33.95,60.24)
  SIG_L10 w0.091: v4(34.54,61.38) 34.54,61.16 v3(34.36,60.97)
  GND_L11 w0.091: v5(34.69,61.74) v4(34.54,61.38)
  BOTTOM w0.114: C16.1 34.76,61.81 v5(34.69,61.74)
N31526000: length 4.5
  TOP w0.114: U17.32 47.73,30.89 47.72,30.9 v2(47.69,30.9)
  INT_L3 w0.254: v2(47.69,30.9) v3(48.63,30.9)
  SIG_L10 w0.254: v5(47.98,30.54) 48.37,30.54 48.63,30.81 v3(48.63,30.9)
  BOTTOM w0.254: v5(47.98,30.54) 46.52,30.54 L13.1
  vias: v4(47.97,31.28) v4(47.97,30.95) v5(47.97,31.28) v5(47.97,30.95)
N31599735: length 6.8
  TOP w0.114: U19.32 45.64,13.36 45.08,12.79 45.08,11.09 44.09,10.1 42.66,10.1 42.27,9.7 L19.1
N31726154: length 1.9
  INT_L3 w0.091: v2(30.55,10.91) 30.55,10.58 v3(30.5,10.53)
  SIG_L10 w0.091: v5(30.07,11.01) 30.07,10.96 v3(30.5,10.53)
  BOTTOM w0.114: C145.1 C146.2
N32045954: length 1.6
  BOTTOM w0.381: R94.1 R93.1 9.97,34.12 C73.1
N32303458: length 1.6
  BOTTOM w0.381: C110.1 R126.1 R127.1
N32341441: length 5.8
  BOTTOM w0.114: R5.1 48.79,60.78 R10.2 R16.2 46.31,60.78 44.04,58.51 D2.1
N32341443: length 4.2
  BOTTOM w0.114: R1.1 47.94,59.8 R10.1 47.91,58.57 47.68,58.34 Q1.1 47.49,58.45 D2.2
N32341445: length 6.1
  BOTTOM w0.114: R6.1 46.35,54.52 R12.2 R17.2 45.35,54.52 44.19,54.52 42.75,53.08 D3.1
N32341447: length 4.6
  BOTTOM w0.114: R12.1 47.19,53.61 R3.1 47.2,52.58 Q2.1 46.61,52.09 D3.2
N32350953: length 1.4
  TOP w0.114: v2(29.81,33.21) 29.83,33.21 U6.Y15
  INT_L3 w0.091: v3(29.35,33.67) v2(29.81,33.21)
  SIG_L10 w0.091: v5(29.84,33.5) 29.74,33.5 29.55,33.5 29.38,33.67 v3(29.35,33.67)
  BOTTOM w0.114: C319.2 29.74,33.5 v5(29.84,33.5)
N32350956: length 1.3
  INT_L3 w0.091: v3(25.01,29.12) 25.82,29.12 v2(25.87,29.17)
  SIG_L10 w0.091: v5(24.55,29.12) v3(25.01,29.12)
N32350987: length 5.6
  INT_L3 w0.091: v3(26.28,23.97) 26.67,24.35 v2(26.67,24.37)
  SIG_L10 w0.091: v3(26.28,23.97) 25.9,23.58 25.35,23.58 25.12,23.36 24.38,23.36 23.36,24.37 22.64,24.37 22.32,24.69 v5(22.32,24.96)
N32350990: length 2
  TOP w0.114: v2(31.08,33.51) 31,33.51 U6.Y14
  INT_L3 w0.091: v3(31.39,33.92) 31.08,33.62 v2(31.08,33.51)
  SIG_L10 w0.091: v3(31.39,33.92) 31.39,33.92 31.04,33.58 v5(30.61,33.58)
N32351019: length 1.2
  INT_L3 w0.091: v3(26.15,28.13) 26.43,28.13 v2(26.66,28.36)
  SIG_L10 w0.091: v3(26.15,28.13) 26.26,28.03 26.26,27.82 v5(26.41,27.67)
  BOTTOM w0.114: 26.33,27.69 26.39,27.69 v5(26.41,27.67)
N32351022: length 2
  INT_L3 w0.091: v2(29.07,24.37) 30,24.37 30.09,24.28 v3(30.09,24.19)
  SIG_L10 w0.091: v3(30.09,24.19) 30.14,24.24 v5(30.14,24.78)
  BOTTOM w0.114: v5(30.14,24.78) 30.19,24.73 C324.1
N32351049: length 1.4
  INT_L3 w0.091: v5(29.02,33.21) 29.02,33.31 28.74,33.59 v3(28.72,33.59)
  SIG_L10 w0.091: v3(28.72,33.59) 29.02,33.29 v5(29.02,33.21)
  BOTTOM w0.114: v5(29.02,33.21) 28.9,33.34 C325.2
N32351052: length 1.2
  TOP w0.114: U6.J10 v2(33.89,24.36)
  INT_L3 w0.091: v2(33.89,24.36) 33.89,24.36 v3(34.26,23.99)
  SIG_L10 w0.091: v3(34.26,23.99) 34.31,23.93 v5(34.74,23.93)
  BOTTOM w0.114: v5(34.74,23.93) 34.74,23.89 34.78,23.85 C326.1
N32351083: length 1.5
  INT_L3 w0.091: v3(34.3,25.5) 34.3,25.5 34.61,25.18 v2(34.66,25.18)
  SIG_L10 w0.091: v3(34.3,25.5) 34.31,25.49 34.31,24.88 v5(34.17,24.74)
  BOTTOM w0.114: v5(34.17,24.74) 34.13,24.7 34.13,24.67 C327.2
N32351086: length 1.4
  INT_L3 w0.091: v2(25.87,29.99) 25.42,29.99 v3(25.39,30.01)
  SIG_L10 w0.091: v3(25.39,30.01) 25.74,30.36 v5(25.78,30.36)
  BOTTOM w0.114: C328.1 v5(25.78,30.36)
N32351113: length 2.7
  TOP w0.114: U6.J9 35.03,24.02 35.19,24.02 v2(35.19,24.01)
  INT_L3 w0.091: v2(35.19,24.01) 35.2,24.02 35.2,24.1 35.42,24.33 35.42,24.42 v3(35.36,24.49)
  SIG_L10 w0.091: v3(35.36,24.49) 35.41,24.49 35.5,24.4 36.11,24.4 v5(36.54,24.83)
N32351116: length 1.5
  INT_L3 w0.091: v2(31.47,33.17) 31.81,33.51 31.81,33.52 v3(31.84,33.55)
  SIG_L10 w0.091: v5(31.46,33.19) 31.46,33.24 31.78,33.55 v3(31.84,33.55)
  BOTTOM w0.114: v5(31.46,33.19) 31.28,33.36 C330.1
N32351145: length 1.2
  INT_L3 w0.091: v2(26.67,25.17) 26.36,24.86 v3(26.36,24.8)
  SIG_L10 w0.091: v3(26.36,24.8) 26.3,24.8 26.2,24.89 v5(26.2,25.18)
  BOTTOM w0.114: C331.2 26.09,25.07 v5(26.2,25.18)
N32351151: length 6.4
  INT_L3 w0.091: v2(29.07,25.18) 29.07,25.24 v3(29.46,25.62)
  SIG_L10 w0.091: v3(29.46,25.62) 29.02,25.18 29.02,23.09 29.36,22.75 29.71,22.75 29.91,22.54 v5(29.91,21.98)
  BOTTOM w0.114: v5(29.91,21.98) 29.96,21.93 C332.1 30.56,21.73 R318.1
N32351171: length 3.6
  TOP w0.114: U6.L9 v2(35.04,26.35)
  INT_L3 w0.091: v3(36.48,25.59) 36.49,25.6 36.49,25.69 35.83,26.35 v2(35.04,26.35)
  SIG_L10 w0.091: v5(37.27,26.36) 36.5,25.59 v3(36.48,25.59)
  BOTTOM w0.114: v5(37.27,26.36) C333.2
N32388958: length 3.4
  TOP w0.114: XP1.183 56.39,59.18 55.57,58.36 R319.1
N32392766: length 3.7
  BOTTOM w0.114: U16.7 33.33,2.64 33.69,2.28 R230.1 R234.2
N32392999: length 3.2
  BOTTOM w0.114: R168.2 34.57,6 34.84,5.73 35.65,5.73 36.22,6.29 R164.1 R170.2
N32637123: length 2.6
  TOP w0.114: v2(34.43,53.4) 34.31,53.53 34.31,54.19 33.94,54.56 U3.C8
  INT_L3 w0.091: v3(34.08,53.18) 34.08,53.23 34.23,53.38 34.41,53.38 v2(34.43,53.4)
  SIG_L10 w0.091: v3(34.08,53.18) 34.08,53.81 v5(34.1,53.84)
N32670742: length 8.4
  TOP w0.114: U3.A3 35.97,58.62 v7(36.16,58.81)
  BOTTOM w0.114: R18.2 42.41,58.13 40.56,58.13 Y1.3 39.12,59.56 C14.1 37.27,59.56 36.52,58.81 v7(36.16,58.81)
N32674796: length 15.2
  TOP w0.114: U3.M11 v2(26.36,51.85)
  INT_L3 w0.091: v2(26.36,51.85) 25.62,51.85 24.48,50.71 21.56,50.71 18.51,53.76 13.81,53.76 v2(13.53,53.48)
N32678230: length 3.6
  TOP w0.114: U3.B12 35.12,51.04 36.87,51.04 37.5,50.41 R35.2
N32680788: length 4.3
  TOP w0.114: U3.C10 34.29,52.72 v2(34.33,52.72)
  INT_L3 w0.091: v2(37.76,52.21) 37.61,52.06 35.02,52.06 34.36,52.72 v2(34.33,52.72)
N32681411: length 3.6
  TOP w0.114: R37.2 38.35,50.81 37.56,50.81 36.95,51.42 U3.A12
N32684937: length 6.2
  TOP w0.114: U3.C13 v2(34.08,50.2)
  INT_L3 w0.091: v2(39.56,49.57) 39.36,49.77 34.51,49.77 v2(34.08,50.2)
N32685500: length 11.7
  TOP w0.114: R46.1 41.63,56.1 ; 41.63,56.1 R47.1 41.72,56.01 ; 41.63,56.1 41.72,56.01 ; 41.72,56.01 41.72,55.72 41.67,55.66 v2(41.67,55.62) ; U3.D8 v2(32.78,54.45)
  INT_L3 w0.091: v2(41.67,55.62) 40.14,54.09 35.68,54.09 35.5,54.27 34.77,54.27 34.7,54.19 33.18,54.19 32.93,54.45 v2(32.78,54.45)
N32689068: length 2
  TOP w0.114: v7(30.36,54.2) 30.36,54.18 30.71,53.82 U3.G9
  BOTTOM w0.114: R43.1 30.38,54.22 v7(30.36,54.2) 30.33,54.2 30.31,54.22 R41.2
N32690150: length 1.3
  TOP w0.114: U3.H9 29.95,53.82 v7(30.32,53.45)
  BOTTOM w0.114: v7(30.32,53.45) 30.32,53.46 R38.2
N32694377: length 2.2
  TOP w0.114: U3.L3 27.49,58.62 27.14,58.97 27.14,59.02 v7(27.13,59.03)
  BOTTOM w0.114: v7(27.13,59.03) 27.13,59.03 27.13,58.97 R29.1 R30.1
N32708016: length 8.8
  TOP w0.114: v2(33.63,52.56) 33.67,52.52 33.67,52.51 U3.C11 ; v2(40.38,52.64) 40.38,52.69 40.91,53.08 TP6.1
  INT_L3 w0.091: v2(40.38,52.64) 40.35,52.64 40.23,52.77 39.79,52.77 38.83,51.81 34.76,51.81 34.05,52.52 33.67,52.52 v2(33.63,52.56)
N32708264: length 4.3
  TOP w0.114: U3.K8 v2(28.31,54.6)
  INT_L3 w0.091: v2(24.22,54.42) 24.5,54.7 26.94,54.7 26.94,54.69 28.22,54.69 v2(28.31,54.6)
N32708462: length 12.6
  TOP w0.114: v2(15.82,53.33) 15.74,53.25 TP10.1 ; U3.N12 v2(25.59,51.12)
  INT_L3 w0.091: v2(15.82,53.33) 15.89,53.4 18.48,53.4 21.58,50.31 24.78,50.31 v2(25.59,51.12)
N32708995: length 1.2
  INT_L3 w0.091: v3(28.87,52.87) 28.82,52.87 28.67,53.02 v2(28.34,53.02)
  SIG_L10 w0.091: v5(28.52,52.54) 28.85,52.87 v3(28.87,52.87)
  BOTTOM w0.114: v5(28.52,52.54) 28.62,52.64 R39.2
N32710130: length 3.3
  TOP w0.114: U4.2 42.7,50.75 R34.1 41.48,50.75 40.59,49.86 R36.1
N32710609: length 2.4
  TOP w0.203: R42.2 25.19,52.22 U3.N11
N32734224: length 8.6
  TOP w0.114: R48.1 R50.2 39.39,52.59 38.69,52.59 38.22,53.06 38.22,53.15 C34.1 ; U3.A10 37.94,53.02 C34.1 ; U3.A9 37.54,53.82 C34.1
N32811364: length 2.9
  TOP w0.114: U1.4 49.56,53.05 C7.1 49.76,52.86 50.13,52.5 R8.1
N32826883: length 1.3
  TOP w0.114: R9.2 D1.2
N32827036: length 13
  TOP w0.114: v2(41.93,54.5) TP7.1
  INT_L3 w0.091: v2(41.93,54.5) 41.29,53.86 35.56,53.86 35.38,54.05 34.86,54.05 34.79,53.97 33.09,53.97 33.01,54.05 32.16,54.05 31.59,54.62 v2(31.54,54.62)
N32966375: length 4.4
  TOP w0.114: U2.1 11.41,60.48 11.22,60.29 9.56,60.29 C5.1 R7.2 8.25,60.52 R2.2
N32966437: length 2.5
  TOP w0.254: U2.7 12.91,65.18 R13.1 R14.1
N32966504: length 2.6
  TOP w0.254: C13.1 R15.2 13.49,60.84 U2.5
N32992437: length 2
  TOP w0.12: R172.1 29.05,16.56 28.27,17.34 U6.A17
N33004530: length 2.2
  TOP w0.114: U6.AB16 v2(28.74,34.4)
  INT_L3 w0.091: v2(28.74,34.4) 28.92,34.58 28.92,34.81 28.87,34.86 v3(28.87,34.91)
  SIG_L10 w0.091: v3(28.87,34.91) 28.87,35.24 28.97,35.34 28.97,35.36 v5(28.99,35.38)
  BOTTOM w0.114: v5(28.99,35.38) 28.97,35.36 28.97,35.34 28.78,35.15 R60.1
N33116208: length 5.2
  TOP w0.114: R56.1 24.54,16.64 v2(24.34,16.84) ; U6.D21 v2(24.71,19.98)
  INT_L3 w0.091: v2(24.71,19.98) 24.71,19.75 25.06,19.39 25.06,19.07 25.04,19.05 25.04,19.02 24.82,18.8 24.63,18.8 24.36,18.53 24.36,17.97 24.6,17.72 24.6,16.98 24.46,16.84 v2(24.34,16.84)
N33266046: length 2
  BOTTOM w0.114: R329.1 R327.1 51.93,53.66 Q8.D
N33266747: length 2
  BOTTOM w0.114: R324.1 54.55,52.47 R323.1 54.27,53.61 Q7.D
N261608581: length 3.6
  TOP w0.12: v8(17.57,32.27) 17.85,31.99 19.86,31.99 U6.V27
  BOTTOM w0.114: v8(17.57,32.27) 17.64,32.35 R99.2
N261608661: length 3.3
  TOP w0.12: v8(17.01,32.3) 17.01,32.19 17.52,31.69 19.35,31.69 U6.V28
  BOTTOM w0.114: v8(17.01,32.3) 17.04,32.27 R100.2
N323928681: length 1.7
  BOTTOM w0.114: R160.2 32.91,7.24 32.92,7.24 33.17,7.49 U13.10
N323929221: length 1.7
  BOTTOM w0.114: R162.2 34.77,7.87 U13.8
N329663413: length 1.5
  TOP w0.254: U2.9 11.91,65.18 R11.2
N330092162: length 2.2
  TOP w0.114: Q3.D 49.2,58.38 D4.1
N330103841: length 1.3
  TOP w0.114: R23.2 D4.2
N330155391: length 14
  TOP w0.114: R227.2 v2(20.03,0.77)
  INT_L3 w0.091: v2(33.24,1.59) 32.76,2.07 24.68,2.07 23.66,1.05 20.31,1.05 v2(20.03,0.78)
N330155500: length 11.4
  TOP w0.114: D5.1 31.78,1.76 32.55,2.53 41.41,2.53 Q4.D
N330160361: length 8.4
  TOP w0.114: R228.2 v2(20.91,0.74)
  INT_L3 w0.091: v2(28.77,1.49) 28.49,1.77 24.78,1.77 23.79,0.78 20.94,0.78 v2(20.91,0.74)
N330160440: length 13.4
  TOP w0.114: Q5.D 39.32,2.77 28.33,2.77 27.45,1.89 D6.1
N330162891: length 3.5
  TOP w0.114: D7.2 24.88,1.19 24.24,0.55 22,0.55 R229.2
N330162970: length 22.2
  TOP w0.114: v2(23.46,2.05) 23.36,1.94 D7.1
  INT_L3 w0.091: v2(44.36,3.26) 39.99,3.26 39.49,2.76 37.66,2.76 37.25,2.35 23.77,2.35 v2(23.46,2.05)
N330247804: length 1.1
  TOP w0.114: U14.5 36.59,4.42 R161.2
N330247805: length 1.1
  TOP w0.114: U14.4 35.94,4.5 R163.2
N3195997380: length 2.9
  TOP w0.114: 7.54,31.82 7.54,29.7 R97.1
  TOP w0.12: U9.L8 7.54,31.82
N3196008080: length 2.7
  TOP w0.114: R96.1 7.51,41.36 7.51,42.99 U8.L8
N3196802080: length 2.8
  TOP w0.114: U10.L8 7.93,9.75 7.51,9.33 7.51,7.52 R129.1
N3196813480: length 3.2
  TOP w0.114: U11.L8 7.93,21.01 7.54,20.61 7.54,19.83 8.65,18.72 R130.1

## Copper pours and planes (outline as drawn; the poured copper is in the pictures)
GND on TOP: 38.96,12.56 38.96,9.67 38.73,9.44 37.91,9.44 37.74,9.26 37.74,8.22 37.89,8.06 38.57,8.06 38.96,8.45 40.35,8.45 40.56,8.65 40.56,10.88 40.45,10.99 39.72,10.99 39.62,11.09 39.62,12.54 39.54,12.61 39.01,12.61
GND on TOP: 8.37,41.69 10.15,41.69 10.25,41.59 10.25,40.75 10.51,40.5 13.81,40.5 14.16,40.86 14.16,41.31 14.39,41.54 14.57,41.54 14.72,41.69 14.72,42.1 14.85,42.23 15.28,42.23 15.38,42.13 15.38,40.63 15.82,40.2 15.82,39 15.46,38.65 10.23,38.65 9.59,38.01 8.91,38.01 8.27,38.65 6.8,38.65 6.57,38.88 6.57,40.25 6.98,40.65 8.09,40.65 8.27,40.83 8.27,41.59
GND on TOP: 49.55,54.78 49.37,54.95 49.37,59.12 48.56,59.93 48.07,59.93 47.9,60.11 47.9,61.4 47.41,61.89 44.77,61.89 44.16,62.5 44.16,65.62 43.65,66.13 41.87,66.13 42.18,66.64 42.35,67.22 51.15,67.22 52.04,66.33 52.04,54.98 51.83,54.78
GND on TOP: 21.84,64.15 24.86,64.15 25.29,63.72 25.29,61.91 24.76,61.38 23.82,61.38 23.26,61.94 22.12,61.94 21.71,62.34 21.71,64.02
GND on TOP: 27.98,58.26 33.29,58.26 33.6,57.95 33.6,53 33.42,52.82 27.2,52.82 27.09,52.92 27.09,53.66 27.47,54.04 27.47,54.72 27.3,54.9 27.3,55.44 27.58,55.72 27.58,55.92 27.3,56.2 27.3,57.57
GND on TOP: 54.07,22.37 54.07,21.76 54.37,21.45 54.75,21.45 55.31,20.89 56.02,20.89 56.25,21.12 56.25,21.88 55.72,22.42 54.12,22.42
GND on TOP: 17.87,48.93 20.39,48.93 20.82,48.5 20.82,43.09 20.26,42.53 18.23,42.53 17.42,43.35 17.42,48.48
GND on TOP: 30.7,12.64 25.26,12.64 21.61,8.98 21.61,4.99 23.66,2.93 32.53,2.93 33.8,4.2 33.8,8.47 33.16,9.11 31.44,9.11 31.26,9.28 31.26,12.08
GND on TOP: 0.38,0.38 0.38,67.22 5.45,67.22 5.45,62.09 4.26,60.9 4.26,54.27 1.95,51.96 1.95,27.5 2.56,26.89 2.56,20.51 1.9,19.85 1.9,16.95 2.4,16.45 2.4,8.75 3.45,7.71 7.28,7.71 7.31,7.68 7.31,6.24 7.08,6.01 7.08,0.57 6.89,0.38
GND on TOP: 14.57,59.4 14.57,54.37 14.67,54.27 15.82,54.27 16.12,54.57 16.12,58.97 17.19,60.03 17.19,62.04 17.11,62.12 16.1,62.12 15.77,62.45 15.77,62.9 15.54,63.13 9.72,63.13 9.24,63.61 9.24,66.71 8.96,66.99 6.32,66.99 5.96,66.64 5.96,63.72 6.01,63.67 6.01,61.23 4.84,60.06 4.84,53.63 5.48,53 7.31,53 7.64,53.33 7.64,60.64 8.09,61.1 9.62,61.1 9.92,61.4 14.09,61.4 14.62,61.94 15.33,61.94 15.51,61.76 15.51,59.75 15.31,59.55 14.72,59.55
GND on BOTTOM: 27.8,58.59 31.23,58.59 31.69,58.13 31.69,57.34 32.05,56.99 32.07,56.99 32.17,56.88 32.17,56.17 32.28,56.07 33.67,56.07 33.88,55.87 33.88,54.93 33.67,54.72 30.6,54.72 29.94,55.39 29.94,56.66 29.61,56.99 29.15,56.99 28.31,57.82 27.8,57.82 27.7,57.93 27.7,58.48
GND on BOTTOM: 23.21,7.63 23.21,11.87 23.72,12.38 24.88,12.38 25.29,11.98 25.29,11.19 25.49,10.99 27.83,10.99 27.91,10.91 27.91,9.67 28.03,9.54 28.62,9.54 28.92,9.23 28.92,8.7 28.41,8.19 28.41,6.03 28.03,5.65 25.26,5.65 25.19,5.58 25.19,4.64 25.42,4.41 27.3,4.41 27.32,4.43 27.75,4 27.75,3.26 27.91,3.11 29.38,3.11 29.84,3.57 29.84,6.03 31.41,7.61 31.41,11.67 29.99,13.09 21.25,13.09 20.72,12.56 20.72,8.57 21.33,7.96 21.96,7.96 22.34,7.58 23.16,7.58
GND on BOTTOM: 36.77,31.61 37.81,31.61 37.94,31.48 37.94,29.53 37.69,29.27 37.66,29.27 37.43,29.05 37.43,28.59 37.36,28.51 35.27,28.51 35.25,28.54 35.25,29.1 35.35,29.2 37.02,29.2 37.18,29.35 37.18,30.06 37,30.24 36.67,30.24 36.59,30.32 36.59,31.43
GND on BOTTOM: 41.14,29.63 41.14,28.21 41.32,28.03 42.26,28.03 42.89,28.66 44.11,28.66 44.31,28.87 44.31,31.64 44.52,31.84 45.31,31.84 45.43,31.97 45.43,33.49 44.67,34.25 44.67,35.47 44.92,35.73 45.53,35.73 45.71,35.9 45.71,36.56 45.66,36.61 44.39,36.61 43.65,35.88 43.65,33.97 42.97,33.29 42.97,30.67 42.05,29.76 41.27,29.76
GND on BOTTOM: 49.01,33.41 53.18,33.41 53.36,33.59 53.89,33.59 54.09,33.39 54.09,30.26 53.92,30.09 51.15,30.09 50.82,29.76 50.21,29.76 49.45,30.52 48.63,30.52 48.45,30.7 48.45,32.86
GND on BOTTOM: 30.34,28.05 31.28,28.05 31.67,27.67 31.67,26.3 31.46,26.1 31.41,26.1 31.31,26 31.31,25.13 31.11,24.93 30.57,24.93 30.17,25.34 30.17,27.88
GND on BOTTOM: 19.78,20 19.78,22.37 18.33,23.81 18.33,30.32 19.24,31.23 24.68,31.23 26.1,29.81 26.1,25.18 25.26,24.35 23.74,24.35 21.81,22.42 21.81,20.21 21.43,19.83 19.96,19.83
GND on BOTTOM: 37.99,23.08 36.97,24.09 36.97,25.08 37.23,25.34 40.76,25.34 40.81,25.29 40.81,23.81 40.07,23.08
GND on BOTTOM: 34.76,0.38 34.76,1.18 36.52,2.93 45.38,2.93 48.43,5.98 51.27,5.98 52.54,4.71 52.54,0.38 42.35,0.38 40,2.38 37.65,0.38
GND on BOTTOM: 30.04,32.88 30.04,31.61 30.22,31.43 30.65,31.43 30.93,31.15 30.93,30.85 31.18,30.59 31.41,30.59 31.44,30.57 31.44,29.99 31.51,29.91 32.38,29.91 32.48,30.01 32.48,30.54 32.71,30.77 34.18,30.77 34.26,30.7 34.26,29.4 33.95,29.1 31.51,29.1 31.39,29.22 30.47,29.22 30.09,28.84 28.85,28.84 28.8,28.89 28.8,29.27 29.18,29.65 29.18,31.15 29.07,31.26 29.07,32.65 29.43,33.01 29.91,33.01
GND on BOTTOM: 30.47,18.63 30.47,16.88 30.93,16.42 31.87,16.42 32.12,16.17 32.12,14.47 32.33,14.26 36.34,14.26 37.02,14.95 37.02,16.5 37.56,17.03 37.61,17.03 37.61,17.49 37.23,17.87 36.77,17.87 36.36,18.28 36.36,18.63 36.21,18.78 30.62,18.78
GND on BOTTOM: 25.85,48.6 25.85,47.64 26.05,47.43 26.59,47.43 27.35,46.67 27.35,44.89 27.73,44.51 31.44,44.51 31.67,44.74 31.67,45.99 31.39,46.27 30.27,46.27 30.07,46.47 30.07,47.74 31.36,49.04 31.36,49.52 31.61,49.77 32.22,49.77 32.5,50.05 32.5,51.02 32.28,51.24 31.06,51.24 30.9,51.09 30.9,49.87 30.55,49.52 28.67,49.52 28.24,49.09 27.6,49.09 27.2,48.68 25.93,48.68
GND on BOTTOM: 27.09,62.12 27.09,59.65 26.76,59.32 26.76,58.86 26.66,58.76 26.08,58.76 26,58.84 26,59.2 25.8,59.4 25.44,59.4 25.19,59.65 25.19,60.74 25.09,60.85 23.99,60.85 23.84,60.69 23.84,50.71 23.64,50.51 22.12,50.51 20.82,49.21 18.15,49.21 17.39,49.97 13.15,49.97 12.72,50.41 12.72,52.41 14.44,54.14 14.44,56.22 14.98,56.76 15.82,56.76 15.97,56.6 15.97,54.95 15.56,54.55 15.56,52.36 16.98,50.94 21.07,50.94 21.58,51.45 21.58,53.61 21,54.19 18.74,54.19 18.51,54.42 18.51,55.79 18.61,55.89 21.2,55.89 21.89,56.58 21.89,59.17 21.33,59.73 15.84,59.73 15.54,60.03 15.54,61.53 16.07,62.07 21.15,62.07 21.63,62.55 21.63,64.05 21.73,64.15 25.01,64.15 25.21,63.94 25.21,63.21 25.95,62.47 26.74,62.47
GND on BOTTOM: 36.92,55.84 36.92,52.85 35.7,51.63 35.7,49.82 36.09,49.44 41.14,49.44 41.37,49.67 41.37,50.61 39.11,52.87 39.11,55.26 39.39,55.54 40.99,55.54 41.27,55.82 41.27,57.04 40.73,57.57 38.52,57.57 38.14,57.19 38.14,56.07 38.02,55.94 37.02,55.94
GND on BOTTOM: 41.09,62.67 40.83,62.93 32.73,62.93 31.89,63.77 31.89,67.22 37.65,67.22 40,65.22 42.35,67.22 43.1,67.22 43.1,66.08 42.1,65.09 42.1,63.23 41.55,62.67
GND on BOTTOM: 47.52,17.06 48.99,17.06 49.22,16.83 49.22,15.94 49.45,15.71 50.99,15.71 51.25,15.96 51.25,16.52 51.33,16.6 51.99,16.6 52.06,16.52 52.06,12.64 51.27,11.85 51.27,9.84 50.87,9.44 47.57,9.44 47.41,9.59 47.41,12.05 47.46,12.1 47.46,12.28 46.8,12.94 46.8,15.38 47.29,15.86 47.29,16.83
GND on BOTTOM: 19.88,39.54 18.48,39.54 18.36,39.66 18.36,47.08 18.71,47.43 22.22,47.43 22.52,47.13 22.52,45.05 22.57,45 24.32,45 24.71,45.38 26.46,45.38 26.66,45.17 26.66,44.18 26.53,44.06 25.06,44.06 24.91,44.21 23.16,44.21 23,44.06 23,41.26 21.25,39.51 19.91,39.51
GND on BOTTOM: 0.38,0.38 0.38,67.22 16.22,67.22 16.22,64.96 15.31,64.05 15.31,58.31 14.67,57.67 5.02,57.67 0.53,53.18 0.53,15.28 2,13.81 2,10.48 1.06,9.54 1.06,6.41 1.24,6.24 6.52,6.24 7.41,5.35 14.83,5.35 15.31,5.83 15.31,7.46 15.43,7.58 17.85,7.58 18.71,6.72 18.71,0.38
GND on BOTTOM: 39.26,41.16 41.47,41.16 42.41,40.22 42.41,37.45 42.1,37.15 41.22,37.15 40.68,37.68 40.68,39.56 40.43,39.81 40.43,40.22 40.35,40.3 39.11,40.3 38.65,39.84 38.65,39.08 38.55,38.98 37.48,38.98 37.08,38.57 37.08,37.83 36.34,37.1 36.34,35.7 36.06,35.42 34.87,35.42 34.69,35.6 34.69,36.23 35.32,36.87 35.32,39.66 35.75,40.09 36.8,40.09 37.08,40.37 37.08,40.68 37.53,41.14 39.23,41.14
GND on BOTTOM: 21.58,35.67 17.49,35.67 16.83,35.01 16.83,33.74 17.26,33.31 18.48,33.31 18.61,33.19 18.61,31.64 18.74,31.51 22.22,31.51 22.47,31.76 22.47,32.8 22.85,33.19 23.77,33.19 23.97,33.39 23.97,34.84 23.59,35.22 22.04,35.22
GND on GND_L2, GND_L4, GND_L9, GND_L11: 0.38,0.38 0.38,67.22 37.65,67.22 40,65.22 42.35,67.22 59.62,67.22 59.62,25.68 56.5,25.68 55.62,24.8 56.5,23.92 59.62,23.92 59.62,0.38 42.35,0.38 40,2.38 37.65,0.38
GND on INT_L3: 40.46,65.26 42.25,66.84 42.31,67.03 42.35,67.22 59.62,67.22 59.62,25.68 56.5,25.68 56.07,25.57 55.74,25.26 55.74,26.38 56.66,26.38 58.13,27.85 58.13,33.74 57.12,34.76 57.12,44.79 58.21,45.89 58.21,62.19 56.33,64.07 51.91,64.07 50.26,62.42 47.54,62.42 45.53,64.43 42.74,64.43 42.26,63.94 38.5,63.94 38.4,64.05 8.48,64.05 6.52,62.09 6.52,56.1 3.09,52.67 2.33,52.67 2.33,30.47 2.66,30.14 2.66,7.51 7.28,2.88 18.2,2.88 19.37,1.71 19.37,0.38 0.38,0.38 0.38,67.22 37.65,67.22 37.84,66.59 38.19,66.04 ; 2 cut-outs
GND on INT_L3: 50.18,31.97 50.18,27.83 50.39,27.62 51.76,27.62 52.19,28.05 52.19,33.49 52.14,33.54 51.76,33.54
GND on INT_L3: 41.06,50.25 41.06,45.71 41.42,45.35 42.64,45.35 43.1,45.81 43.1,48.7 43.63,49.24 43.63,49.97 43.17,50.43 41.24,50.43
GND on INT_L3: 47.01,15.2 51.43,15.2 51.63,15 51.63,10.86 52.6,9.89 52.6,7.33 51.83,6.57 47.95,6.57 47.64,6.87 47.64,9.84 45.99,11.49 45.99,14.19
GND on PWR_L7: 0.38,0.38 0.38,67.22 37.65,67.22 40,65.22 42.35,67.22 59.62,67.22 59.62,25.68 56.5,25.68 55.62,24.8 56.5,23.92 59.62,23.92 59.62,0.38 42.35,0.38 40,2.38 37.65,0.38 ; 1 cut-out
GND on SIG_L8: 0.38,0.38 0.38,67.22 37.65,67.22 38.01,66.29 38.72,65.59 38.45,65.32 28.54,65.32 24.43,61.2 16.68,61.2 14.93,59.45 14.93,54.6 13.5,53.18 4.94,53.18 3.6,51.83 3.6,41.62 4.84,40.37 14.72,40.37 16.32,38.77 16.32,32.47 15.23,31.38 5.4,31.38 2.18,28.16 2.18,20.28 2.84,19.62 24.25,19.62 25.29,18.58 25.29,16.32 26.56,15.05 30.8,15.05 32.61,13.25 32.61,5.68 33.62,4.66 38.19,4.66 40.96,7.43 54.86,7.43 58.59,11.16 59.62,11.16 59.62,0.38 42.35,0.38 40,2.38 37.65,0.38
GND on SIG_L10: 0.38,0.38 0.38,67.22 37.65,67.22 40,65.22 42.35,67.22 51.38,67.22 51.38,63.18 50.49,62.29 47.46,62.29 46.5,63.26 36.31,63.26 34.26,61.2 8.27,61.2 1.77,54.7 1.77,10.38 1.39,10 1.39,6.52 2.61,5.3 22.22,5.3 24.73,2.78 42.61,2.78 43.58,1.82 43.58,0.38 42.35,0.38 40,2.38 37.65,0.38
VDD_1V8 on BOTTOM: 34.79,28.31 36.59,28.31 36.8,28.11 36.8,27.52 36.03,26.76 35.04,26.76 34.71,27.09 34.71,28.23
